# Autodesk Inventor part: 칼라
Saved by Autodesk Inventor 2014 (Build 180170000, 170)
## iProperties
Created: 2026-07
Part Number: 칼라
Material: 강철, 연강
Document SubType Name: Modeling
Designer: dg
Density: 7.86 g/cm^3
Appearance: 강철
Mass: 24.5695 g
Surface Area: 24.0825 cm^2
Volume: 3.12588 cm^3
Author: jhkim
Creation Date: 2026-07-02
Sending System: Autodesk Inventor 2027
Preprocessor: ST-DEVELOPER v20.1
Author: dg
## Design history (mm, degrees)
node "칼라1"
node "솔리드1"
node "기준1"
